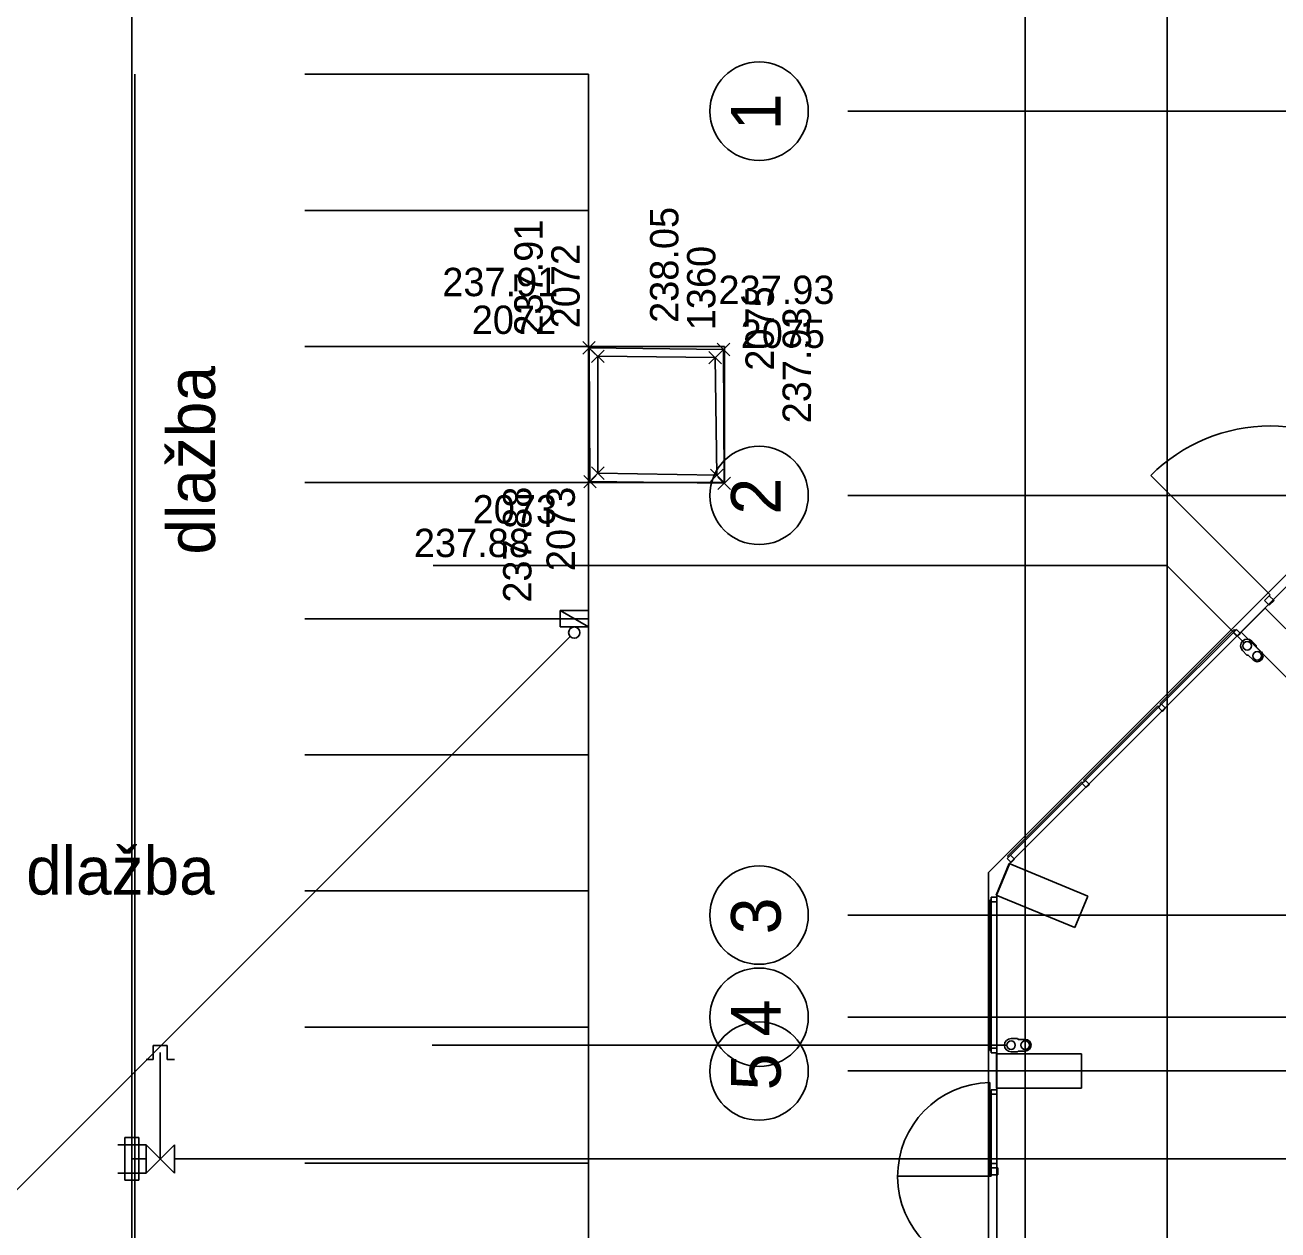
# Model space of a CAD drawing. Extents: x -264205 to -263659, y -1242401 to -1241986.
# Drawn here: x -263926.03 to -263903.94, y -1242107.68 to -1242086.44 of the extents above; entities that cross this region are included whole.
import ezdxf

# ---------------------------------------------------------------- set-up
doc = ezdxf.new("R2010")
doc.units = 0
for name, color, linetype in [('BOD_CISLO_2-2', 7, 'Continuous'), ('BOD_CISLO_2-3', 7, 'Continuous'), ('BOD_SYMBOL_2-2', 7, 'Continuous'), ('BOD_SYMBOL_2-3', 7, 'Continuous'), ('BOD_VYSKA_2-2', 7, 'Continuous'), ('BOD_VYSKA_2-3', 7, 'Continuous'), ('HESCON_OSI_STAVBY_KFA', 7, 'Continuous'), ('POPIS_2-2', 7, 'Continuous'), ('POPIS_2-3', 7, 'Continuous'), ('PROJEKT_OBRUBNIKY_KOMUNIKACIE', 7, 'Continuous'), ('PROJEKT_TDZ_VODOROVNE', 7, 'Continuous'), ('RAM_NA_TLAC_2-3_1-250', 7, 'Continuous'), ('SITUACIA_DSP_2D', 7, 'Continuous'), ('SO_20-4_OBRUBNIKY_DOLNA_HRANA', 7, 'Continuous'), ('SO_20-4_OBRUBNIKY_HORNA_HRANA', 7, 'Continuous')]:
    doc.layers.add(name, color=color, linetype=linetype)

msp = doc.modelspace()

# ---------------------------------------------------------------- linework, layer by layer
at = {"layer": 'BOD_SYMBOL_2-2'}
for p, q in [((-263916.193, -1242092.241), (-263915.973, -1242092.019)), ((-263915.973, -1242092.241), (-263916.193, -1242092.019)), ((-263913.822, -1242092.271), (-263913.601, -1242092.049)), ((-263913.601, -1242092.271), (-263913.822, -1242092.049)), ((-263916.041, -1242092.39), (-263915.819, -1242092.17)), ((-263915.819, -1242092.39), (-263916.041, -1242092.17)), ((-263913.97, -1242092.414), (-263913.75, -1242092.194)), ((-263913.75, -1242092.414), (-263913.97, -1242092.194)), ((-263916.038, -1242094.453), (-263915.817, -1242094.231)), ((-263915.817, -1242094.453), (-263916.038, -1242094.231)), ((-263913.941, -1242094.49), (-263913.72, -1242094.269)), ((-263913.72, -1242094.49), (-263913.941, -1242094.269)), ((-263916.177, -1242094.6), (-263915.957, -1242094.38)), ((-263915.957, -1242094.6), (-263916.177, -1242094.38)), ((-263913.812, -1242094.63), (-263913.59, -1242094.41)), ((-263913.59, -1242094.63), (-263913.812, -1242094.41))]:
    msp.add_line(p, q, dxfattribs=at)
at = {"layer": 'BOD_SYMBOL_2-3'}
for p, q in [((-263915.973, -1242092.241), (-263916.193, -1242092.019)), ((-263915.973, -1242092.019), (-263916.193, -1242092.241)), ((-263913.601, -1242092.271), (-263913.822, -1242092.049)), ((-263913.601, -1242092.049), (-263913.822, -1242092.271)), ((-263915.819, -1242092.39), (-263916.041, -1242092.17)), ((-263915.819, -1242092.17), (-263916.041, -1242092.39)), ((-263913.75, -1242092.414), (-263913.97, -1242092.194)), ((-263913.75, -1242092.194), (-263913.97, -1242092.414)), ((-263915.817, -1242094.453), (-263916.038, -1242094.231)), ((-263915.817, -1242094.231), (-263916.038, -1242094.453)), ((-263913.72, -1242094.49), (-263913.941, -1242094.269)), ((-263913.72, -1242094.269), (-263913.941, -1242094.49)), ((-263915.957, -1242094.6), (-263916.177, -1242094.38)), ((-263915.957, -1242094.38), (-263916.177, -1242094.6)), ((-263913.59, -1242094.63), (-263913.812, -1242094.41)), ((-263913.59, -1242094.41), (-263913.812, -1242094.63))]:
    msp.add_line(p, q, dxfattribs=at)
at = {"layer": 'HESCON_OSI_STAVBY_KFA'}
for p, q in [((-263908.393, -1242083.237), (-263908.393, -1242246.707)), ((-263792.653, -1242087.957), (-263911.523, -1242087.957)), ((-263792.653, -1242094.732), (-263911.523, -1242094.732)), ((-263792.653, -1242102.132), (-263911.523, -1242102.132)), ((-263792.653, -1242103.932), (-263911.523, -1242103.932)), ((-263792.653, -1242104.882), (-263911.523, -1242104.882))]:
    msp.add_line(p, q, dxfattribs=at)
for centre in [(-263913.085, -1242087.958), (-263913.085, -1242094.733), (-263913.085, -1242102.133), (-263913.085, -1242103.933), (-263913.085, -1242104.883)]:
    msp.add_circle(centre, 0.867, dxfattribs=at)
at = {"layer": 'PROJEKT_OBRUBNIKY_KOMUNIKACIE'}
for p, q in [((-263916.093, -1242092.107), (-263913.693, -1242092.107)), ((-263916.093, -1242094.507), (-263916.093, -1242092.107)), ((-263913.693, -1242092.107), (-263913.693, -1242094.507)), ((-263913.693, -1242094.507), (-263916.093, -1242094.507))]:
    msp.add_line(p, q, dxfattribs=at)
msp.add_lwpolyline([(-263794.893, -1242227.382), (-263808.968, -1242241.457), (-263894.968, -1242241.457), (-263909.043, -1242227.382), (-263909.043, -1242196.333), (-263914.143, -1242196.333), (-263914.143, -1242132.433), (-263909.043, -1242132.433), (-263909.043, -1242101.382), (-263894.968, -1242087.307), (-263808.968, -1242087.307), (-263794.893, -1242101.382), (-263794.893, -1242227.382)], dxfattribs=at)
at = {"layer": 'PROJEKT_TDZ_VODOROVNE'}
for p, q in [((-263924.088, -1242241.458), (-263924.093, -1242087.307)), ((-263921.093, -1242087.308), (-263916.093, -1242087.308)), ((-263916.093, -1242087.308), (-263916.093, -1242141.207)), ((-263921.093, -1242089.707), (-263916.093, -1242089.707)), ((-263921.093, -1242092.107), (-263916.093, -1242092.107)), ((-263921.093, -1242094.507), (-263916.093, -1242094.507)), ((-263921.093, -1242096.907), (-263916.093, -1242096.907)), ((-263921.093, -1242099.307), (-263916.093, -1242099.307)), ((-263921.093, -1242101.707), (-263916.093, -1242101.707)), ((-263921.093, -1242104.107), (-263916.093, -1242104.107)), ((-263921.093, -1242106.507), (-263916.093, -1242106.507))]:
    msp.add_line(p, q, dxfattribs=at)
at = {"layer": 'RAM_NA_TLAC_2-3_1-250'}
msp.add_lwpolyline([(-263980.139, -1242275.511), (-263980.139, -1241985.511), (-263905.889, -1241985.511), (-263905.889, -1242275.511)], close=True, dxfattribs=at)
at = {"layer": 'SITUACIA_DSP_2D'}
for p, q in [((-263924.143, -1242082.64), (-263924.143, -1242185.14)), ((-263909.043, -1242101.382), (-263894.968, -1242087.307)), ((-263908.663, -1242101.215), (-263895.135, -1242087.687)), ((-263916.093, -1242092.107), (-263913.693, -1242092.107)), ((-263916.093, -1242094.507), (-263916.093, -1242092.107)), ((-263913.693, -1242092.107), (-263913.693, -1242094.507)), ((-263913.693, -1242094.507), (-263916.093, -1242094.507)), ((-263904.074, -1242096.484), (-263906.177, -1242094.38)), ((-263905.894, -1242095.971), (-263918.832, -1242095.971)), ((-263904.533, -1242097.332), (-263905.894, -1242095.971)), ((-263904.091, -1242096.501), (-263904.074, -1242096.484)), ((-263904.176, -1242096.586), (-263904.091, -1242096.501)), ((-263904.091, -1242096.671), (-263904.176, -1242096.586)), ((-263904.091, -1242096.501), (-263904.006, -1242096.586)), ((-263904.006, -1242096.586), (-263904.091, -1242096.671)), ((-263916.593, -1242097.052), (-263916.593, -1242096.762)), ((-263916.593, -1242096.762), (-263916.093, -1242096.762)), ((-263916.093, -1242097.052), (-263916.593, -1242096.762)), ((-263916.093, -1242097.052), (-263916.593, -1242096.762)), ((-263916.593, -1242096.762), (-263916.593, -1242097.052)), ((-263916.093, -1242096.762), (-263916.093, -1242097.052)), ((-263904.586, -1242097.143), (-263904.162, -1242096.719)), ((-263904.162, -1242096.719), (-263903.101, -1242097.779)), ((-263916.093, -1242097.052), (-263916.593, -1242097.052)), ((-263916.593, -1242097.052), (-263916.093, -1242097.052)), ((-263904.711, -1242097.1), (-263906.019, -1242098.408)), ((-263906.001, -1242098.426), (-263904.693, -1242097.118)), ((-263904.698, -1242097.123), (-263904.726, -1242097.151)), ((-263904.726, -1242097.151), (-263904.656, -1242097.222)), ((-263904.693, -1242097.118), (-263904.711, -1242097.1)), ((-263904.67, -1242097.095), (-263904.698, -1242097.123)), ((-263904.599, -1242097.165), (-263904.67, -1242097.095)), ((-263903.526, -1242098.203), (-263904.586, -1242097.143)), ((-263916.414, -1242097.223), (-263926.239, -1242107.049)), ((-263904.656, -1242097.222), (-263904.599, -1242097.165)), ((-263904.319, -1242097.381), (-263904.397, -1242097.303)), ((-263904.484, -1242097.547), (-263904.563, -1242097.468)), ((-263904.563, -1242097.468), (-263904.484, -1242097.547)), ((-263904.465, -1242097.547), (-263904.484, -1242097.547)), ((-263904.376, -1242097.635), (-263904.465, -1242097.547)), ((-263904.319, -1242097.401), (-263904.319, -1242097.381)), ((-263904.231, -1242097.489), (-263904.319, -1242097.401)), ((-263906.055, -1242098.444), (-263907.363, -1242099.752)), ((-263907.345, -1242099.77), (-263906.037, -1242098.462)), ((-263906.037, -1242098.462), (-263906.055, -1242098.444)), ((-263906.017, -1242098.442), (-263906.046, -1242098.47)), ((-263906.046, -1242098.47), (-263905.975, -1242098.541)), ((-263906.019, -1242098.408), (-263906.001, -1242098.426)), ((-263905.989, -1242098.414), (-263906.017, -1242098.442)), ((-263905.918, -1242098.485), (-263905.989, -1242098.414)), ((-263905.975, -1242098.541), (-263905.918, -1242098.485)), ((-263908.703, -1242101.092), (-263907.395, -1242099.784)), ((-263907.377, -1242099.802), (-263908.685, -1242101.11)), ((-263907.395, -1242099.784), (-263907.377, -1242099.802)), ((-263907.361, -1242099.786), (-263907.39, -1242099.814)), ((-263907.363, -1242099.752), (-263907.345, -1242099.77)), ((-263907.333, -1242099.758), (-263907.361, -1242099.786)), ((-263907.262, -1242099.828), (-263907.333, -1242099.758)), ((-263907.39, -1242099.814), (-263907.319, -1242099.885)), ((-263907.319, -1242099.885), (-263907.262, -1242099.828)), ((-263908.68, -1242101.105), (-263908.709, -1242101.134)), ((-263908.709, -1242101.134), (-263908.638, -1242101.204)), ((-263908.685, -1242101.11), (-263908.703, -1242101.092)), ((-263908.652, -1242101.077), (-263908.68, -1242101.105)), ((-263908.581, -1242101.148), (-263908.652, -1242101.077)), ((-263908.674, -1242101.225), (-263908.903, -1242101.779)), ((-263908.893, -1242101.769), (-263908.663, -1242101.215)), ((-263907.288, -1242101.799), (-263908.674, -1242101.225)), ((-263908.638, -1242101.204), (-263908.581, -1242101.148)), ((-263909.043, -1242132.433), (-263909.043, -1242101.382)), ((-263908.903, -1242101.779), (-263907.518, -1242102.353)), ((-263908.893, -1242125.432), (-263908.893, -1242101.769)), ((-263909.018, -1242101.872), (-263909.018, -1242104.522)), ((-263908.993, -1242101.872), (-263909.018, -1242101.872)), ((-263908.993, -1242101.859), (-263908.993, -1242101.819)), ((-263908.993, -1242101.819), (-263908.893, -1242101.819)), ((-263908.993, -1242101.899), (-263908.993, -1242101.859)), ((-263908.993, -1242104.522), (-263908.993, -1242101.872)), ((-263908.893, -1242101.899), (-263908.993, -1242101.899)), ((-263908.893, -1242101.819), (-263908.893, -1242101.899)), ((-263907.518, -1242102.353), (-263907.288, -1242101.799)), ((-263923.768, -1242104.682), (-263923.768, -1242104.432)), ((-263923.768, -1242104.432), (-263923.518, -1242104.432)), ((-263923.518, -1242104.432), (-263923.518, -1242104.682)), ((-263908.718, -1242104.427), (-263918.846, -1242104.427)), ((-263908.643, -1242104.31), (-263908.532, -1242104.31)), ((-263908.532, -1242104.31), (-263908.643, -1242104.31)), ((-263908.518, -1242104.324), (-263908.532, -1242104.31)), ((-263908.393, -1242104.324), (-263908.518, -1242104.324)), ((-263923.643, -1242106.432), (-263923.643, -1242104.557)), ((-263909.018, -1242104.522), (-263908.993, -1242104.522)), ((-263908.993, -1242104.522), (-263908.993, -1242104.482)), ((-263908.993, -1242104.482), (-263908.893, -1242104.482)), ((-263908.993, -1242104.562), (-263908.993, -1242104.522)), ((-263908.893, -1242104.562), (-263908.993, -1242104.562)), ((-263908.898, -1242105.182), (-263908.898, -1242104.582)), ((-263908.898, -1242104.582), (-263907.398, -1242104.582)), ((-263908.893, -1242104.482), (-263908.893, -1242104.562)), ((-263908.532, -1242104.544), (-263908.643, -1242104.544)), ((-263908.518, -1242104.53), (-263908.532, -1242104.544)), ((-263908.393, -1242104.53), (-263908.518, -1242104.53)), ((-263907.398, -1242104.582), (-263907.398, -1242105.182)), ((-263923.768, -1242104.682), (-263923.893, -1242104.682)), ((-263923.518, -1242104.682), (-263923.393, -1242104.682)), ((-263909.018, -1242105.087), (-263909.018, -1242106.737)), ((-263909.018, -1242106.552), (-263909.018, -1242105.252)), ((-263909.018, -1242105.252), (-263908.993, -1242105.252)), ((-263908.893, -1242105.212), (-263908.993, -1242105.212)), ((-263908.993, -1242105.212), (-263908.993, -1242105.252)), ((-263908.993, -1242105.252), (-263908.993, -1242106.552)), ((-263908.993, -1242105.252), (-263908.993, -1242105.292)), ((-263908.993, -1242105.292), (-263908.893, -1242105.292)), ((-263907.398, -1242105.182), (-263908.898, -1242105.182)), ((-263908.893, -1242105.292), (-263908.893, -1242105.212)), ((-263923.893, -1242106.182), (-263924.393, -1242106.182)), ((-263924.018, -1242106.057), (-263924.268, -1242106.057)), ((-263924.268, -1242106.057), (-263924.268, -1242106.807)), ((-263924.018, -1242106.807), (-263924.018, -1242106.057)), ((-263923.893, -1242106.682), (-263923.893, -1242106.182)), ((-263923.893, -1242106.182), (-263923.393, -1242106.682)), ((-263923.393, -1242106.182), (-263923.893, -1242106.682)), ((-263923.393, -1242106.682), (-263923.393, -1242106.182)), ((-263924.143, -1242106.432), (-263923.893, -1242106.432)), ((-263923.893, -1242106.432), (-263924.143, -1242106.432)), ((-263923.393, -1242106.432), (-263903.343, -1242106.432)), ((-263908.993, -1242106.552), (-263909.018, -1242106.552)), ((-263908.993, -1242106.552), (-263908.993, -1242106.512)), ((-263908.993, -1242106.512), (-263908.893, -1242106.512)), ((-263908.993, -1242106.592), (-263908.993, -1242106.552)), ((-263908.893, -1242106.592), (-263908.993, -1242106.592)), ((-263908.873, -1242106.592), (-263908.993, -1242106.592)), ((-263908.993, -1242106.592), (-263908.993, -1242106.712)), ((-263908.893, -1242106.512), (-263908.893, -1242106.592)), ((-263908.873, -1242106.712), (-263908.873, -1242106.592)), ((-263923.893, -1242106.682), (-263924.393, -1242106.682)), ((-263924.268, -1242106.807), (-263924.018, -1242106.807)), ((-263908.993, -1242106.737), (-263910.643, -1242106.737)), ((-263908.993, -1242106.712), (-263908.993, -1242106.737)), ((-263908.993, -1242106.712), (-263908.873, -1242106.712))]:
    msp.add_line(p, q, dxfattribs=at)
for centre, radius in [((-263916.343, -1242097.152), 0.1), ((-263904.48, -1242097.385), 0.075), ((-263904.303, -1242097.562), 0.075), ((-263908.643, -1242104.427), 0.075), ((-263908.393, -1242104.427), 0.075)]:
    msp.add_circle(centre, radius, dxfattribs=at)
for centre, radius, start, end in [((-263904.074, -1242096.484), 2.975, 44.9999, 134.9999), ((-263904.48, -1242097.385), 0.117, 45, 225), ((-263904.303, -1242097.562), 0.103, 225, 45), ((-263908.643, -1242104.427), 0.117, 90, 270), ((-263908.393, -1242104.427), 0.103, 270, 90), ((-263908.993, -1242106.737), 1.65, 90.8682, 270)]:
    msp.add_arc(centre, radius, start, end, dxfattribs=at)
at = {"layer": 'SO_20-4_OBRUBNIKY_DOLNA_HRANA'}
msp.add_line((-263916.083, -1242092.13), (-263913.711, -1242092.16), dxfattribs=at)
msp.add_lwpolyline([(-263916.083, -1242092.13), (-263916.067, -1242094.49), (-263913.701, -1242094.52), (-263913.711, -1242092.16)], dxfattribs=at)
at = {"layer": 'SO_20-4_OBRUBNIKY_HORNA_HRANA'}
msp.add_line((-263915.93, -1242092.28), (-263913.86, -1242092.304), dxfattribs=at)
msp.add_lwpolyline([(-263915.93, -1242092.28), (-263915.927, -1242094.342), (-263913.83, -1242094.379), (-263913.86, -1242092.304)], dxfattribs=at)

# ---------------------------------------------------------------- texts
at = {"layer": 'BOD_CISLO_2-2'}
for s, p in [('2072', (-263918.151, -1242091.886)), ('2075', (-263913.41, -1242092.133)), ('2073', (-263918.135, -1242095.228))]:
    msp.add_text(s, height=0.5, dxfattribs=at).set_placement(p)
at = {"layer": 'BOD_CISLO_2-3'}
for s, p in [('2072', (-263916.249, -1242091.786)), ('1360', (-263913.855, -1242091.821)), ('2075', (-263912.825, -1242092.534)), ('2073', (-263916.333, -1242096.068))]:
    msp.add_text(s, height=0.5, rotation=90, dxfattribs=at).set_placement(p)
at = {"layer": 'BOD_VYSKA_2-2'}
for s, p in [('237.91', (-263918.67, -1242091.22)), ('237.93', (-263913.801, -1242091.358)), ('237.88', (-263919.171, -1242095.821))]:
    msp.add_text(s, height=0.5, dxfattribs=at).set_placement(p)
at = {"layer": 'BOD_VYSKA_2-3'}
for s, p in [('238.05', (-263914.507, -1242091.691)), ('237.91', (-263916.901, -1242091.915)), ('237.93', (-263912.171, -1242093.462)), ('237.88', (-263917.098, -1242096.624))]:
    msp.add_text(s, height=0.5, rotation=90, dxfattribs=at).set_placement(p)
at = {"layer": 'HESCON_OSI_STAVBY_KFA'}
for s, p in [('1', (-263912.704, -1242088.298)), ('2', (-263912.704, -1242095.073)), ('3', (-263912.704, -1242102.473)), ('4', (-263912.704, -1242104.273)), ('5', (-263912.704, -1242105.223))]:
    msp.add_text(s, height=0.875, rotation=90, dxfattribs=at).set_placement(p)
at = {"layer": 'POPIS_2-2'}
msp.add_text('dlažba', height=0.8438, dxfattribs=at).set_placement((-263926.007, -1242101.771))
at = {"layer": 'POPIS_2-3'}
msp.add_text('dlažba', height=0.8438, rotation=90, dxfattribs=at).set_placement((-263922.676, -1242095.777))

doc.saveas('drawing.dxf')
